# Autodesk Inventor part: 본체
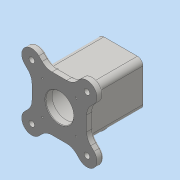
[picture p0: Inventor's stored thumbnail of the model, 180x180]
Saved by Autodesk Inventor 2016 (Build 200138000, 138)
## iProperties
Created: 2019-11
Part Number: 본체
Material: 일반
Document SubType Name: Modeling
Designer: user
Density: 1 g/cm^3
Appearance: 기본값
Mass: 398.62 g
Surface Area: 879.96 cm^2
Volume: 398.62 cm^3
Author: user
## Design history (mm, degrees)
sketch "스케치2"
  geometry: L1 (-49, 49)-(49, 49); L2 (49, 49)-(49, -49); L3 (49, -49)-(-49, -49); L4 (-49, -49)-(-49, 49); L5 (-49, 49)-(49, -49); L6 (49, 49)-(-49, -49); L7 (49.497, 49.497)-(-49.497, -49.497); L8 (36.77, 62.225)-(-62.225, -36.77); L9 (-36.77, -62.225)-(62.225, 36.77); L10 (49.497, -49.497)-(-49.497, 49.497); L11 (62.225, -36.77)-(-36.77, 62.225); L12 (-62.225, 36.77)-(36.77, -62.225); A1 r 18 centre (49.497, 49.497) between (62.225, 36.77) and (36.77, 62.225); A2 r 18 centre (-49.497, -49.497) between (-62.225, -36.77) and (-36.77, -62.225); A3 r 18 centre (49.497, -49.497) between (36.77, -62.225) and (62.225, -36.77); A4 r 18 centre (-49.497, 49.497) between (-36.77, 62.225) and (-62.225, 36.77); 1 further point
  constraints: 28 end point, 8 point on circle, 8 tangent, 4 centre point, 4 midpoint, 4 parallel, 2 perpendicular, 1 horizontal, 1 point on line
  dimensions: "d7" = 98 distance of L2.end L3.end; "d8" = 98 distance of L1.end L2.end; "d9" = 18 radius of A3; "d10" = 18 radius of A1; "d11" = 70 distance of point (0, 0) L7.start; "d12" = 70 distance of point (0, 0) L10.start
extrude "돌출1" new body sketch "스케치2" distance "d13" = 12; taper "d14" = 0 deg
sketch "스케치3"
  geometry: L1 (-40, 40)-(40, 40); L2 (40, 40)-(40, -40); L3 (40, -40)-(-40, -40); L4 (-40, -40)-(-40, 40); L5 (-40, 40)-(40, -40); L6 (40, 40)-(-40, -40); 1 further point
  constraints: 12 end point, 2 midpoint, 2 parallel, 1 horizontal, 1 perpendicular
  dimensions: "d19" = 80 distance of L1.start L1.end; "d20" = 80 distance of L1.end L2.end
extrude "돌출2" join sketch "스케치3" distance "d21" = 98; taper "d22" = 0 deg
sketch "스케치4"
  geometry: C1 r 25 at (0, 0); 1 further point
  constraints: 1 centre point, 1 coincident
  dimensions: "d23" = 50 diameter of C1
extrude "돌출3" cut sketch "스케치4" distance "d24" = 12; taper "d25" = 0 deg
node "작업 평면1"
sketch "스케치5"
  geometry: C1 r 35 at (0, 0); 1 further point
  constraints: 1 centre point, 1 coincident
  dimensions: "d27" = 70 diameter of C1
extrude "돌출4" cut sketch "스케치5" distance "d28" = 86; taper "d29" = 0 deg
chamfer "모따기1" distance "d30" = 1; stored, may be unused: second distance "d31" = 2, angle "d32" = 45 deg
chamfer "모따기2" distance "d33" = 1; stored, may be unused: second distance "d34" = 2, angle "d35" = 45 deg
sketch "스케치6"
  geometry: L1 (-30, 30)-(30, 30); L2 (30, 30)-(30, -30); L3 (30, -30)-(-30, -30); L4 (-30, -30)-(-30, 30); L5 (-30, 30)-(30, -30); L6 (30, 30)-(-30, -30); 2 further points
  constraints: 12 end point, 2 midpoint, 2 parallel, 1 coincident, 1 horizontal, 1 perpendicular
  dimensions: "d36" = 60 distance of L1.start L1.end; "d37" = 60 distance of L1.end L2.end
hole "구멍1" sketch "스케치6" at (-30, 30) diameter "d38" = 3.242; stored, may be unused: countersink angle "d42" = 90 deg, drill point angle "d44" = 118 deg; dims "d39" = 8, "d40" = 4, "d41" = 2, "d43" = 10
node "작업 평면2"
sketch "스케치8"
  geometry: L1 (-36.77, 12)-(-67.497, 12) reference; C1 r 20 at (0, 61); 2 further points
  constraints: 1 centre point, 1 vertical alignment
  dimensions: "d53" = 40 diameter of C1; "d54" = 49 distance from line of L1 C1.centre
extrude "돌출5" join sketch "스케치8" stored distance "d55" = 86; taper "d56" = 0 deg
sketch "스케치9"
  geometry: L1 (-66.636, -49)-(-29.544, -49) reference; L2 (-29.544, -49)-(-29.544, -61) reference; L3 (-29.544, -61)-(-66.636, -61) reference; L4 (-66.636, -61)-(-66.636, -49) reference; L5 (29.544, -49)-(66.636, -49) reference; L6 (66.636, -49)-(66.636, -61) reference; L7 (66.636, -61)-(29.544, -61) reference; L8 (29.544, -61)-(29.544, -49) reference; C1 r 20 at (0, 0) reference; 2 further points
  constraints: 1 coincident
hole "구멍2" sketch "스케치9" at (0, 0) diameter "d57" = 25; stored, may be unused: countersink angle "d61" = 90 deg, drill point angle "d63" = 0 deg; dims "d58" = 8, "d59" = 30, "d60" = 8, "d62" = 40
sketch "스케치10"
  geometry: L1 (40, -40)-(-40, -40) reference; L2 (-40, -40)-(-40, 40) reference; L3 (-40, 40)-(40, 40) reference; L4 (40, 40)-(40, -40) reference; L5 (49, 23.544)-(49, -23.544) reference; L6 (49, -23.544)-(62.225, -36.77) reference; L7 (36.77, -62.225)-(23.544, -49) reference; L8 (23.544, -49)-(-23.544, -49) reference; L9 (-23.544, -49)-(-36.77, -62.225) reference; L10 (-62.225, -36.77)-(-49, -23.544) reference; L11 (-49, -23.544)-(-49, 23.544) reference; L12 (-49, 23.544)-(-62.225, 36.77) reference; L13 (-36.77, 62.225)-(-23.544, 49) reference; L14 (-23.544, 49)-(23.544, 49) reference; L15 (23.544, 49)-(36.77, 62.225) reference; L16 (62.225, 36.77)-(49, 23.544) reference; C1 r 35 at (0, 0) reference; C2 r 25 at (0, 0) reference; A1 r 18 centre (49.497, -49.497) between (36.77, -62.225) and (62.225, -36.77) reference; A2 r 18 centre (-49.497, -49.497) between (-62.225, -36.77) and (-36.77, -62.225) reference; A3 r 18 centre (-49.497, 49.497) between (-36.77, 62.225) and (-62.225, 36.77) reference; A4 r 18 centre (49.497, 49.497) between (62.225, 36.77) and (36.77, 62.225) reference; 2 further points
  constraints: 1 coincident
hole "구멍3" sketch "스케치10" at (-49.497, 49.497) diameter "d64" = 10; stored, may be unused: countersink angle "d68" = 90 deg, drill point angle "d70" = 0 deg; dims "d65" = 8, "d66" = 18, "d67" = 4, "d69" = 40
fillet "모깎기1" dims "d74" = 25
chamfer "모따기3" distance "d75" = 1; stored, may be unused: second distance "d76" = 2, angle "d77" = 45 deg
sketch "스케치11"
  geometry: L1 (80, 98)-(0, 98) reference; 2 further points
  constraints: 1 vertical alignment, 1 other
  dimensions: "d78" = 10 distance from line of L1 point (40, 88)
feature "엠보싱1" sketch "스케치11" dims "d7" = 98, "d8" = 98, "d9" = 18, "d10" = 18, "d11" = 70, "d12" = 70, "d79" = 0.5, "d80" = 0
fillet "모깎기2" dims "d81" = 3
fillet "모깎기3" dims "d82" = 3
fillet "모깎기4" dims "d83" = 10
fillet "모깎기5" dims "d84" = 3
node "솔리드1"
mirror "대칭1"
pattern_linear "직사각형 패턴1" dims "d47" = 60
mirror "대칭2"
pattern_circular "원형 패턴1" dims angle "d72" = 360 deg
node "절단 모서리 투영1"
node "절단 모서리 투영2"
other parameters: "d26" = -55, "d52" = -55
